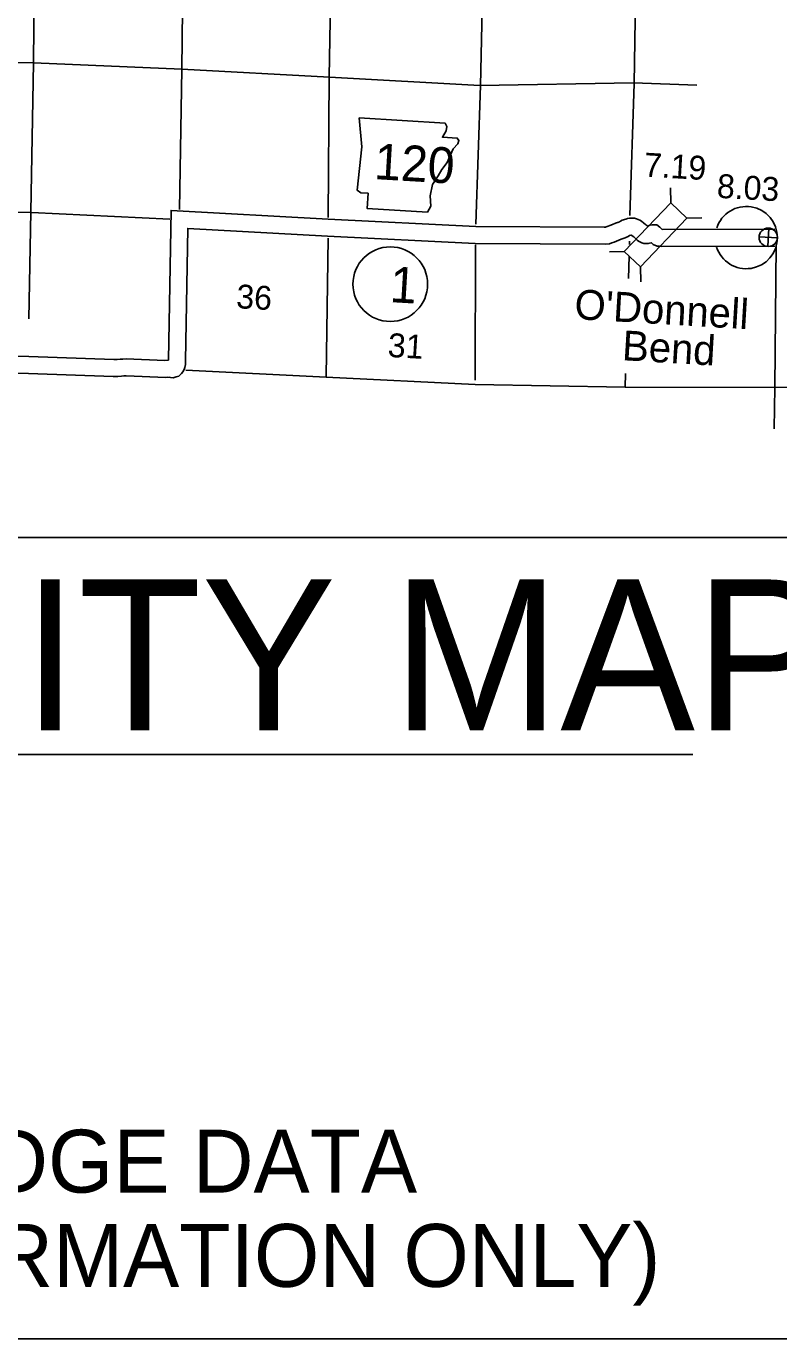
# Model space of a CAD drawing. Extents: x 1366406 to 1373462, y 376856 to 381998.
# Drawn here: x 1368242.9 to 1368458.3, y 380244.8 to 380620.7 of the extents above; entities that cross this region are included whole.
import ezdxf

# ---------------------------------------------------------------- set-up
doc = ezdxf.new("R2010")
doc.units = 0
for name, color, linetype in [('10', 7, 'Continuous'), ('20', 7, 'Continuous'), ('21', 7, 'Continuous'), ('24', 7, 'Continuous'), ('25', 7, 'Continuous'), ('26', 7, 'Continuous'), ('27', 7, 'Continuous'), ('4', 7, 'Continuous'), ('5', 7, 'Continuous'), ('58', 7, 'Continuous'), ('R_Draft', 7, 'Continuous'), ('R_No Plot', 7, 'Continuous')]:
    doc.layers.add(name, color=color, linetype=linetype)

msp = doc.modelspace()

# ---------------------------------------------------------------- linework, layer by layer
at = {"layer": '10'}
for points in [[(1368283.65, 380525.1), (1368284.4, 380567.96), (1368329.39, 380565.43), (1368371.58, 380563.36), (1368408.35, 380563.14), (1368408.82, 380563.19), (1368408.97, 380563.24), (1368409.46, 380563.42), (1368410, 380563.65), (1368410.71, 380563.94), (1368411.56, 380564.31), (1368412.14, 380564.47), (1368412.29, 380564.54), (1368412.7, 380564.73), (1368413.06, 380564.86), (1368413.53, 380565.16), (1368414.52, 380565.5), (1368414.99, 380565.64), (1368415.7, 380565.77), (1368416.37, 380565.75), (1368417.02, 380565.71), (1368417.61, 380565.55), (1368418.1, 380565.37), (1368418.53, 380565.15), (1368419.05, 380564.86), (1368419.75, 380564.28), (1368420.05, 380564.03), (1368420.24, 380563.85), (1368420.58, 380563.62), (1368420.73, 380563.44), (1368420.76, 380563.45), (1368421.46, 380563.72), (1368422.12, 380563.81), (1368423.43, 380563.79), (1368424.27, 380563.15), (1368424.52, 380562.95), (1368424.8, 380562.68), (1368424.93, 380562.54), (1368424.97, 380562.5), (1368457.21, 380562.56)], [(1368283.26, 380520.21), (1368284.21, 380520.11), (1368284.98, 380520), (1368285.83, 380520.28), (1368286.61, 380520.52), (1368287.35, 380521.23), (1368287.73, 380521.71), (1368288.15, 380522.44), (1368288.32, 380523.01), (1368288.55, 380523.82), (1368288.51, 380524.91), (1368289.17, 380562.82), (1368329.13, 380560.58), (1368371.44, 380558.5), (1368408.61, 380558.28), (1368409.85, 380558.42), (1368410.55, 380558.65), (1368411.24, 380558.9), (1368411.87, 380559.16), (1368412.59, 380559.46), (1368413.18, 380559.71), (1368413.8, 380559.88), (1368414.34, 380560.13), (1368414.58, 380560.24), (1368415.23, 380560.48), (1368415.65, 380560.75), (1368416.02, 380560.87), (1368416.11, 380560.9), (1368416.15, 380560.9), (1368416.17, 380560.9), (1368416.21, 380560.87), (1368416.3, 380560.83), (1368416.64, 380560.54), (1368416.83, 380560.39), (1368417.2, 380560.03), (1368417.31, 380559.96), (1368417.45, 380559.8), (1368417.77, 380559.49), (1368418.21, 380559.15), (1368418.74, 380558.84), (1368419.14, 380558.69), (1368419.75, 380558.48), (1368420.23, 380558.47), (1368420.42, 380558.47), (1368420.98, 380558.49), (1368421.36, 380558.58), (1368421.82, 380558.67), (1368421.89, 380558.7), (1368422.42, 380558.23), (1368423.54, 380557.75), (1368424.19, 380557.68), (1368424.79, 380557.64), (1368457.21, 380557.7)], [(1368283.65, 380525.1), (1368282.63, 380524.95), (1368271.55, 380525.42), (1368270.54, 380525.41), (1368269.77, 380525.32), (1368268.9, 380525.28), (1368268.41, 380525.26), (1368268, 380525.28), (1368243.68, 380526.16), (1368222.97, 380526.49), (1368222.21, 380526.57), (1368221.73, 380526.67), (1368220.54, 380526.92), (1368200.97, 380527.35), (1368194.18, 380528.21), (1368192.5, 380528.34), (1368190.04, 380528.3), (1368160.22, 380529.18)], [(1368283.85, 380520.22), (1368282.88, 380520.08), (1368271.49, 380520.56), (1368270.85, 380520.55), (1368270.15, 380520.48), (1368269.15, 380520.43), (1368268.41, 380520.39), (1368267.78, 380520.42), (1368243.55, 380521.3), (1368222.68, 380521.63), (1368221.44, 380521.76), (1368220.73, 380521.91), (1368219.99, 380522.07), (1368200.6, 380522.49), (1368193.68, 380523.38), (1368192.35, 380523.48), (1368190.01, 380523.44), (1368160.56, 380524.31)]]:
    msp.add_lwpolyline(points, dxfattribs=at)
at = {"layer": '20'}
for p, q in [((1368427.4, 380570.13), (1368427.3, 380574.41)), ((1368432.05, 380565.71), (1368436.32, 380565.81)), ((1368414.12, 380556.2), (1368409.85, 380556.1)), ((1368418.77, 380551.78), (1368418.87, 380547.5))]:
    msp.add_line(p, q, dxfattribs=at)
msp.add_lwpolyline([(1368418.77, 380551.78), (1368432.05, 380565.71), (1368427.4, 380570.13), (1368414.12, 380556.2)], close=True, dxfattribs=at)
at = {"layer": '21'}
msp.add_lwpolyline([(1368338.21, 380594.44), (1368338.96, 380586.16), (1368337.68, 380573.75), (1368338.73, 380573), (1368340.78, 380572.88), (1368340.52, 380568.5), (1368357.76, 380567.49), (1368358.69, 380569.22), (1368358.58, 380572.11), (1368359.19, 380575.36), (1368360.84, 380577.87), (1368361.91, 380579.73), (1368363.4, 380581.7), (1368364.35, 380583.85), (1368365.14, 380585.58), (1368366.46, 380587.02), (1368366.79, 380587.96), (1368366.28, 380588.67), (1368362.04, 380588.92), (1368363.11, 380590.78), (1368363.32, 380592), (1368362.81, 380592.98)], close=True, dxfattribs=at)
at = {"layer": '24'}
msp.add_arc((1368449.04, 380560.18), 8.91, 197.6669, 161.9649, dxfattribs=at)
at = {"layer": '26'}
for p, q in [((1368455.17, 380557.64), (1368455.48, 380562.9)), ((1368452.69, 380560.42), (1368457.95, 380560.11))]:
    msp.add_line(p, q, dxfattribs=at)
msp.add_circle((1368455.32, 380560.27), 2.63, dxfattribs=at)
at = {"layer": '27'}
msp.add_circle((1368347.12, 380546.84), 10.69, dxfattribs=at)
at = {"layer": '4'}
for points in [[(1368331.43, 380754.29), (1368331.3, 380735.78), (1368330.81, 380692.86), (1368330.42, 380649.14), (1368329.67, 380606.26), (1368329.36, 380565.9)], [(1368329.3, 380560.06), (1368328.82, 380520.36), (1368328.82, 380520.13)], [(1368288.63, 380522.18), (1368328.76, 380520.25), (1368371.38, 380518.1), (1368414.38, 380517.31), (1368457.17, 380517.23), (1368468.32, 380517.5)]]:
    msp.add_lwpolyline(points, dxfattribs=at)
at = {"layer": '5'}
for points in [[(1368371.63, 380564.05), (1368372.92, 380603.76), (1368373.95, 380647.69), (1368373.97, 380691.44), (1368374.29, 380735.05), (1368374.66, 380753.05)], [(1368289.35, 380749.9), (1368289.2, 380737.19), (1368288.61, 380694.1), (1368287.93, 380651.36), (1368287.46, 380608.43), (1368286.82, 380568.2)], [(1368417.68, 380733.89), (1368417.92, 380691.25), (1368417.63, 380647.12), (1368416.94, 380604.29), (1368415.66, 380566.48)], [(1368246.37, 380722.18), (1368245.86, 380695.61), (1368245.35, 380652.84), (1368245.01, 380610.1), (1368244.25, 380567.56), (1368243.7, 380536.92)], [(1368162.08, 380612.48), (1368201.7, 380610.48), (1368245.02, 380610.21), (1368287.46, 380608.43)], [(1368287.46, 380608.43), (1368329.7, 380606.14), (1368372.72, 380603.74), (1368416.71, 380604.46), (1368434.84, 380603.87)], [(1368160.81, 380569.56), (1368201.31, 380567.9), (1368244.39, 380567.41), (1368284.06, 380565.43)], [(1368371.38, 380519.33), (1368371.52, 380558.09)], [(1368415.6, 380558.24), (1368415.62, 380559.15)], [(1368457.59, 380558.1), (1368457.17, 380517.23), (1368456.99, 380505.37)], [(1368415.31, 380548.51), (1368415.5, 380554.85)], [(1368414.38, 380517.31), (1368414.5, 380521.25)], [(1368414.38, 380517.31), (1368414.5, 380521.25)]]:
    msp.add_lwpolyline(points, dxfattribs=at)
at = {"layer": 'R_Draft'}
for p, q in [((1368086.27, 380412.11), (1368433.74, 380412.11)), ((1367846.32, 380244.81), (1368707.16, 380244.81))]:
    msp.add_line(p, q, dxfattribs=at)
at = {"layer": 'R_No Plot'}
msp.add_lwpolyline([(1367869.99, 380474.3), (1367869.99, 381160.75), (1368650.02, 381160.75), (1368650.02, 380474.3), (1367869.99, 380474.3)], dxfattribs=at)

# ---------------------------------------------------------------- texts
at = {"layer": '21'}
msp.add_text('120', height=10.264, rotation=356.6294, dxfattribs=at).set_placement((1368342.34, 380576.95))
at = {"layer": '24'}
for s, p in [("O'Donnell", (1368399.69, 380536.87)), ('Bend', (1368413.32, 380525.08))]:
    msp.add_text(s, height=8.554, rotation=356.6294, dxfattribs=at).set_placement(p)
at = {"layer": '25'}
msp.add_text('8.03', height=6.843, rotation=356.6294, dxfattribs=at).set_placement((1368440.49, 380571.61))
at = {"layer": '27'}
msp.add_text('1', height=10.26, rotation=356.6294, dxfattribs=at).set_placement((1368346.81, 380541.72))
at = {"layer": '5'}
for s, p in [('36', (1368302.9, 380539.99)), ('31', (1368346.28, 380526.03))]:
    msp.add_text(s, height=6.843, rotation=356.6294, dxfattribs=at).set_placement(p)
at = {"layer": '58'}
msp.add_text('7.19', height=6.843, rotation=356.6294, dxfattribs=at).set_placement((1368419.59, 380577.69))
at = {"layer": 'R_Draft'}
for s, height, p in [('VICINITY MAP', 43.2, (1368087.7, 380419.07)), ('BRIDGE DATA', 18, (1368191.63, 380286.67)), ('(FOR INFORMATION ONLY)', 18, (1368110.21, 380259.67))]:
    msp.add_text(s, height=height, dxfattribs=at).set_placement(p)

doc.saveas('drawing.dxf')
